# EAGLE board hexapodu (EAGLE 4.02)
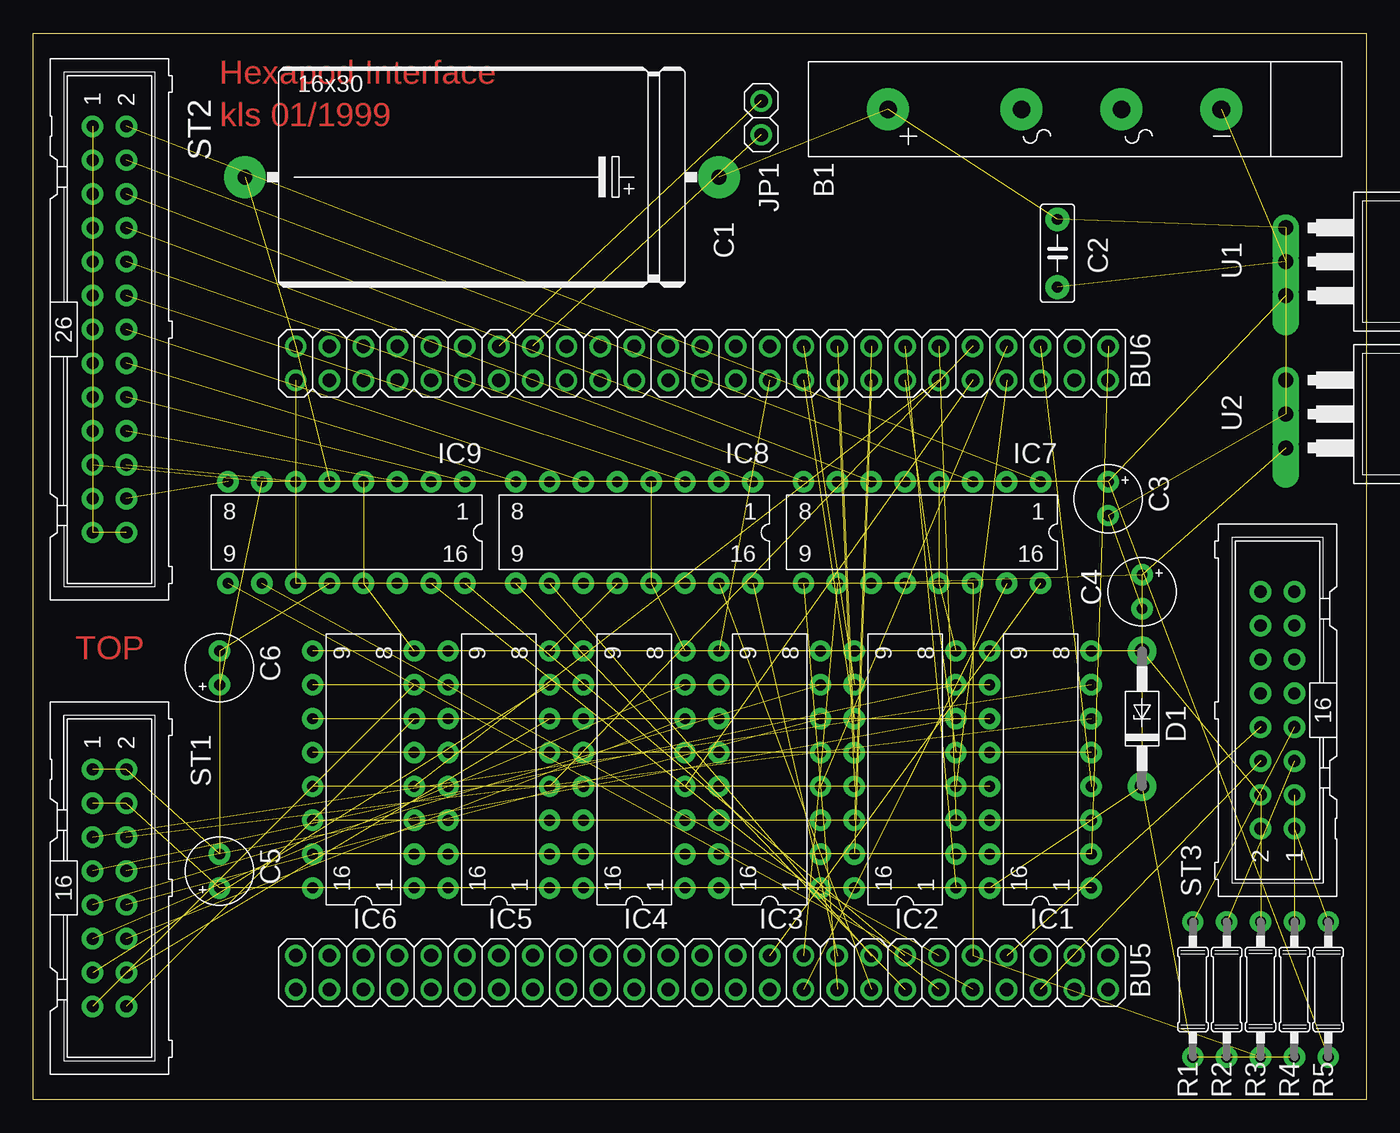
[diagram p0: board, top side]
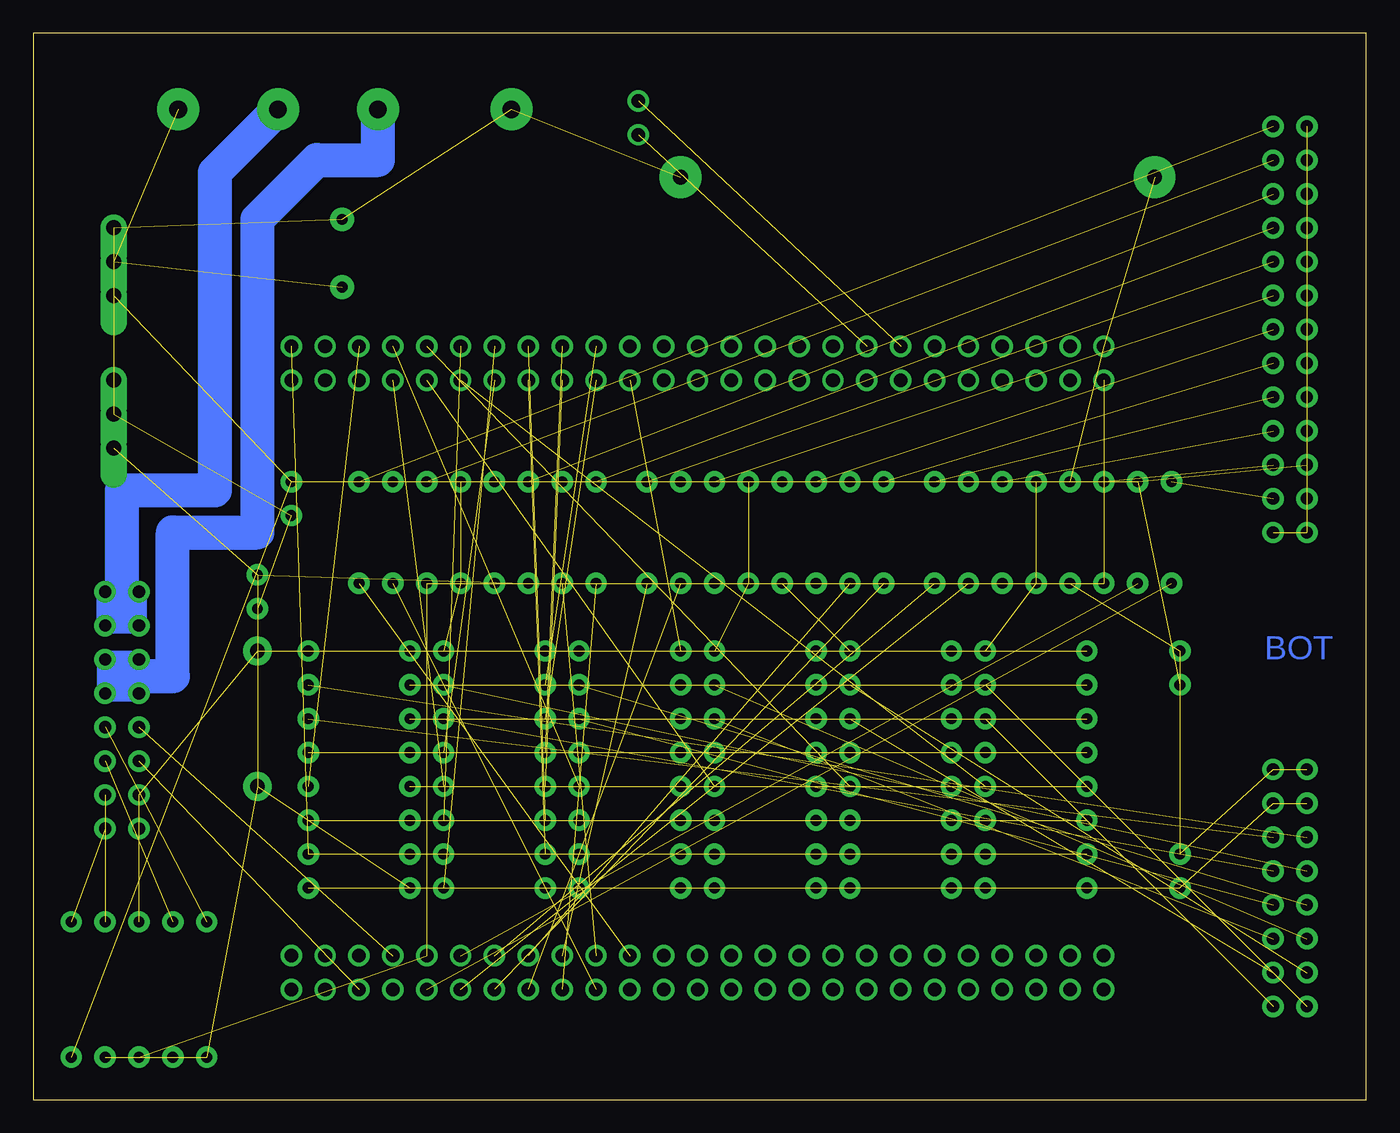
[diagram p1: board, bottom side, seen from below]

Size 100 x 80 mm. Coordinates in mm from the lower left corner, seen from the top.
Outline: 0,0 0,80 100,80 100,0 0,0
Copper layers used: Bottom
Net classes: 1 AC: width 1.27 mm, drill 0.406 mm; 2 Power: width 0.762 mm, drill 0.254 mm, clearance 0.813 mm
tRestrict: area 13.3,72.4 to 41.3,78.7

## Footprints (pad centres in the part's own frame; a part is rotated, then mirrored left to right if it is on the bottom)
FB100 = drill 1.321 pad 3.15 round: + 0,0; - 24.994,0; AC1 10.008,0; AC2 17.501,0
2X25 = drill 1.016 pad 1.6 round: 1 -30.48,-1.27; 2 -30.48,1.27; 3 -27.94,-1.27; 4 -27.94,1.27; 5 -25.4,-1.27; 6 -25.4,1.27; 7 -22.86,-1.27; 8 -22.86,1.27; 9 -20.32,-1.27; 10 -20.32,1.27; 11 -17.78,-1.27; 12 -17.78,1.27; 13 -15.24,-1.27; 14 -15.24,1.27; 15 -12.7,-1.27; 16 -12.7,1.27; 17 -10.16,-1.27; 18 -10.16,1.27; 19 -7.62,-1.27; 20 -7.62,1.27; 21 -5.08,-1.27; 22 -5.08,1.27; 23 -2.54,-1.27; 24 -2.54,1.27; 25 0,-1.27; 26 0,1.27; 27 2.54,-1.27; 28 2.54,1.27; 29 5.08,-1.27; 30 5.08,1.27; 31 7.62,-1.27; 32 7.62,1.27; 33 10.16,-1.27; 34 10.16,1.27; 35 12.7,-1.27; 36 12.7,1.27; 37 15.24,-1.27; 38 15.24,1.27; 39 17.78,-1.27; 40 17.78,1.27; 41 20.32,-1.27; 42 20.32,1.27; 43 22.86,-1.27; 44 22.86,1.27; 45 25.4,-1.27; 46 25.4,1.27; 47 27.94,-1.27; 48 27.94,1.27; 49 30.48,-1.27; 50 30.48,1.27
E35-16 = drill 1.118 pad 3.15 round: + -17.78,0; - 17.78,0
C5B2,5A = drill 0.813 pad 1.778 round: 1 -2.54,0; 2 2.54,0
E2,5-5 = drill 0.813 pad 1.6 round: + -1.27,0; - 1.27,0
DO41Z10 = drill 1.118 pad 2.159 round: A 5.08,0; K -5.08,0
DIL-16 = drill 0.813 pad 1.6 round: 1 -8.89,-3.81; 2 -6.35,-3.81; 3 -3.81,-3.81; 4 -1.27,-3.81; 5 1.27,-3.81; 6 3.81,-3.81; 7 6.35,-3.81; 8 8.89,-3.81; 9 8.89,3.81; 10 6.35,3.81; 11 3.81,3.81; 12 1.27,3.81; 13 -1.27,3.81; 14 -3.81,3.81; 15 -6.35,3.81; 16 -8.89,3.81
1X02 = drill 1.016 pad 1.6 round: 1 -1.27,0; 2 1.27,0
0207/10 = drill 0.813 pad 1.6 round: 1 -5.08,0; 2 5.08,0
0207/10@1 = drill 0.813 pad 1.6 round: 1 -5.08,0; 2 5.08,0
ML16 = drill 0.914 pad 1.6 round: 1 -8.89,-1.27; 2 -8.89,1.27; 3 -6.35,-1.27; 4 -6.35,1.27; 5 -3.81,-1.27; 6 -3.81,1.27; 7 -1.27,-1.27; 8 -1.27,1.27; 9 1.27,-1.27; 10 1.27,1.27; 11 3.81,-1.27; 12 3.81,1.27; 13 6.35,-1.27; 14 6.35,1.27; 15 8.89,-1.27; 16 8.89,1.27
ML26 = drill 0.914 pad 1.6 round: 1 -15.24,-1.27; 2 -15.24,1.27; 3 -12.7,-1.27; 4 -12.7,1.27; 5 -10.16,-1.27; 6 -10.16,1.27; 7 -7.62,-1.27; 8 -7.62,1.27; 9 -5.08,-1.27; 10 -5.08,1.27; 11 -2.54,-1.27; 12 -2.54,1.27; 13 0,-1.27; 14 0,1.27; 15 2.54,-1.27; 16 2.54,1.27; 17 5.08,-1.27; 18 5.08,1.27; 19 7.62,-1.27; 20 7.62,1.27; 21 10.16,-1.27; 22 10.16,1.27; 23 12.7,-1.27; 24 12.7,1.27; 25 15.24,-1.27; 26 15.24,1.27
TO220H = drill 1.118 pad 2 offset: 1 -2.54,-6.35; 2 0,-6.35; 3 2.54,-6.35 | hole 3.302: 0,11.176

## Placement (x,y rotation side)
B1  FB100  [FB100]  64.14,74.3 0 top
BU5  PINHD-2X25  [2X25]  50.16,9.53 180 top
BU6  PINHD-2X25  [2X25]  50.16,55.24 180 top
C1  2200uF/35V  [E35-16]  33.66,69.22 180 top
C2  100nf  [C5B2,5A]  76.83,63.5 90 top
C3  4,7uf/35V  [E2,5-5]  80.64,45.09 270 top
C4  4,7uf/10V  [E2,5-5]  83.19,38.1 270 top
C5  4,7uf/10V  [E2,5-5]  13.97,17.14 90 top
C6  4,7uf/35V  [E2,5-5]  13.97,32.38 90 top
D1  BZX85  [DO41Z10]  83.19,28.57 90 top
IC1  HCTL2016  [DIL-16]  75.56,24.77 90 top
IC2  HCTL2016  [DIL-16]  65.41,24.77 90 top
IC3  HCTL2016  [DIL-16]  55.24,24.77 90 top
IC4  HCTL2016  [DIL-16]  45.09,24.77 90 top
IC5  HCTL2016  [DIL-16]  34.92,24.77 90 top
IC6  HCTL2016  [DIL-16]  24.77,24.77 90 top
IC7  DS3668  [DIL-16]  66.67,42.55 180 top
IC8  DS3668  [DIL-16]  45.09,42.55 180 top
IC9  DS3668  [DIL-16]  23.5,42.55 180 top
JP1  PINHD-1X2  [1X02]  54.61,73.66 270 top
R1  0207/10  [0207/10]  87,8.26 90 top
R2  0207/10  [0207/10]  89.53,8.26 90 top
R3  10k  [0207/10@1]  92.08,8.26 270 top
R4  0207/10  [0207/10]  94.61,8.26 90 top
R5  0207/10  [0207/10]  97.16,8.26 90 top
ST1  PINHD-2X8  [ML16]  5.71,15.88 270 top
ST2  PINHD-2X13  [ML26]  5.71,57.78 270 top
ST3  PINHD-2X8  [ML16]  93.34,29.21 90 top
U1  78S24  [TO220H]  100.33,62.87 270 top
U2  7805  [TO220H]  100.33,51.44 270 top

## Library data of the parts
B1 = RECTIF
BU5 BU6 JP1 = PINHEAD
C1 C3-C6 = ELKO
C2 = CAP-WI
D1 = diode
IC1-IC9 = klaus
R1-R5 = R
ST1-ST3 = ST-ML
U1 U2 = LINEAR

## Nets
+5V: BU6.50 C4.+ C5.+ D1.K IC1.16 IC2.16 IC3.16 IC4.16 IC5.16 IC6.16 IC7.11 IC8.11 IC9.11 R1.1 R2.1 R4.1 ST1.3 ST1.4 U2.3
+24V [Power]: C3.+ C6.+ IC7.2 IC7.7 IC8.2 IC8.7 IC9.2 IC9.7 R5.1 ST2.1 ST2.3 ST2.5 ST2.7 ST2.9 ST2.11 ST2.13 ST2.15 ST2.17 ST2.19 ST2.21 ST2.23 ST2.25 ST2.26 U1.3
AC1 [AC]: B1.AC1 ST3.9 ST3.10 ST3.11 ST3.12
AC2 [AC]: B1.AC2 ST3.13 ST3.14 ST3.15 ST3.16
CLK: BU6.1 IC1.2 IC2.2 IC3.2 IC4.2 IC5.2 IC6.2
COIL0: IC7.1 ST2.2
COIL1: IC7.3 ST2.4
COIL2: IC7.6 ST2.6
COIL3: IC7.8 ST2.8
COIL4: IC8.1 ST2.10
COIL5: IC8.3 ST2.12
COIL6: IC8.6 ST2.14
COIL7: IC8.8 ST2.16
COIL8: IC9.1 ST2.18
COIL9: IC9.3 ST2.20
COIL10: IC9.6 ST2.22
COIL11: IC9.8 ST2.24
D0: BU6.13 IC1.1 IC2.1 IC3.1 IC4.1 IC5.1 IC6.1
D1: BU6.16 IC1.15 IC2.15 IC3.15 IC4.15 IC5.15 IC6.15
D2: BU6.15 IC1.14 IC2.14 IC3.14 IC4.14 IC5.14 IC6.14
D3: BU6.18 IC1.13 IC2.13 IC3.13 IC4.13 IC5.13 IC6.13
D4: BU6.17 IC1.12 IC2.12 IC3.12 IC4.12 IC5.12 IC6.12
D5: BU6.20 IC1.11 IC2.11 IC3.11 IC4.11 IC5.11 IC6.11
D6: BU6.19 IC1.10 IC2.10 IC3.10 IC4.10 IC5.10 IC6.10
D7: BU6.22 IC1.9 IC2.9 IC3.9 IC4.9 IC5.9 IC6.9
EN: BU5.9 IC7.14 IC8.14 IC9.14 R3.2
ENC0: IC1.7 ST1.5
ENC1: IC1.6 ST1.6
ENC2: IC2.7 ST1.7
ENC3: IC2.6 ST1.8
ENC4: IC3.7 ST1.9
ENC5: IC3.6 ST1.10
ENC6: IC4.7 ST1.11
ENC7: IC4.6 ST1.12
ENC8: IC5.7 ST1.13
ENC9: IC5.6 ST1.14
ENC10: IC6.7 ST1.15
ENC11: IC6.6 ST1.16
GND [Power]: B1.- BU6.49 C1.- C2.1 C3.- C4.- C5.- C6.- D1.A IC1.8 IC2.8 IC3.8 IC4.8 IC5.8 IC6.8 IC7.4 IC7.5 IC7.12 IC7.13 IC8.4 IC8.5 IC8.12 IC8.13 IC9.4 IC9.5 IC9.12 IC9.13 R3.1 ST1.1 ST1.2 ST3.2 ST3.4 U1.2 U2.2
N$4: R5.2 ST3.1
N$5: R4.2 ST3.3
N$6: R2.2 ST3.5
N$7: R1.2 ST3.7
N$8: BU6.35 JP1.2
N$9: BU6.37 JP1.1
OE\0: BU6.5 IC1.4
OE\1: BU6.8 IC2.4
OE\2: BU6.7 IC3.4
OE\3: BU6.10 IC4.4
OE\4: BU6.9 IC5.4
OE\5: BU6.12 IC6.4
RST\: BU6.14 IC1.5 IC2.5 IC3.5 IC4.5 IC5.5 IC6.5
SEL: BU6.11 IC1.3 IC2.3 IC3.3 IC4.3 IC5.3 IC6.3
STATUS0: BU5.7 ST3.8
STATUS1: BU5.6 ST3.6
VALVE0: BU5.21 IC7.16
VALVE1: BU5.20 IC7.15
VALVE2: BU5.19 IC7.10
VALVE3: BU5.18 IC7.9
VALVE4: BU5.17 IC8.16
VALVE5: BU5.16 IC8.15
VALVE6: BU5.15 IC8.10
VALVE7: BU5.14 IC8.9
VALVE8: BU5.13 IC9.16
VALVE9: BU5.12 IC9.15
VALVE10: BU5.11 IC9.10
VALVE11: BU5.10 IC9.9
VIN [Power]: B1.+ C1.+ C2.2 U1.1 U2.1

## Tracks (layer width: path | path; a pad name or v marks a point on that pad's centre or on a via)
+5V  (18 unrouted)
+24V  (23 unrouted)
AC1
  Bottom 1.27: ST3.10 ST3.9 ST3.11 ST3.12 92.08,31.75 ST3.10
  Bottom 1.524: ST3.10 ST3.11 | ST3.12 ST3.9
  Bottom 2.54: B1.AC1 74.14,70.48 78.74,70.48 83.19,66.04 83.19,42.55 89.53,42.55 89.53,31.75 92.08,31.75
AC2
  Bottom 1.27: ST3.14 ST3.13 ST3.15 93.34,38.1 ST3.16 ST3.14
  Bottom 1.524: ST3.14 ST3.15 | ST3.13 ST3.16
  Bottom 2.54: 93.34,38.1 93.34,45.72 86.36,45.72 86.36,69.57 B1.AC2
CLK  (6 unrouted)
COIL0  (1 unrouted)
COIL1  (1 unrouted)
COIL2  (1 unrouted)
COIL3  (1 unrouted)
COIL4  (1 unrouted)
COIL5  (1 unrouted)
COIL6  (1 unrouted)
COIL7  (1 unrouted)
COIL8  (1 unrouted)
COIL9  (1 unrouted)
COIL10  (1 unrouted)
COIL11  (1 unrouted)
D0  (6 unrouted)
D1  (6 unrouted)
D2  (6 unrouted)
D3  (6 unrouted)
D4  (6 unrouted)
D5  (6 unrouted)
D6  (6 unrouted)
D7  (6 unrouted)
EN  (4 unrouted)
ENC0  (1 unrouted)
ENC1  (1 unrouted)
ENC2  (1 unrouted)
ENC3  (1 unrouted)
ENC4  (1 unrouted)
ENC5  (1 unrouted)
ENC6  (1 unrouted)
ENC7  (1 unrouted)
ENC8  (1 unrouted)
ENC9  (1 unrouted)
ENC10  (1 unrouted)
ENC11  (1 unrouted)
GND  (33 unrouted)
N$4  (1 unrouted)
N$5  (1 unrouted)
N$6  (1 unrouted)
N$7  (1 unrouted)
N$8  (1 unrouted)
N$9  (1 unrouted)
OE\0  (1 unrouted)
OE\1  (1 unrouted)
OE\2  (1 unrouted)
OE\3  (1 unrouted)
OE\4  (1 unrouted)
OE\5  (1 unrouted)
RST\  (6 unrouted)
SEL  (6 unrouted)
STATUS0  (1 unrouted)
STATUS1  (1 unrouted)
VALVE0  (1 unrouted)
VALVE1  (1 unrouted)
VALVE2  (1 unrouted)
VALVE3  (1 unrouted)
VALVE4  (1 unrouted)
VALVE5  (1 unrouted)
VALVE6  (1 unrouted)
VALVE7  (1 unrouted)
VALVE8  (1 unrouted)
VALVE9  (1 unrouted)
VALVE10  (1 unrouted)
VALVE11  (1 unrouted)
VIN  (4 unrouted)

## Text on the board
Top: Hexapod Interface | kls 01/1999 | TOP
Bottom: BOT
